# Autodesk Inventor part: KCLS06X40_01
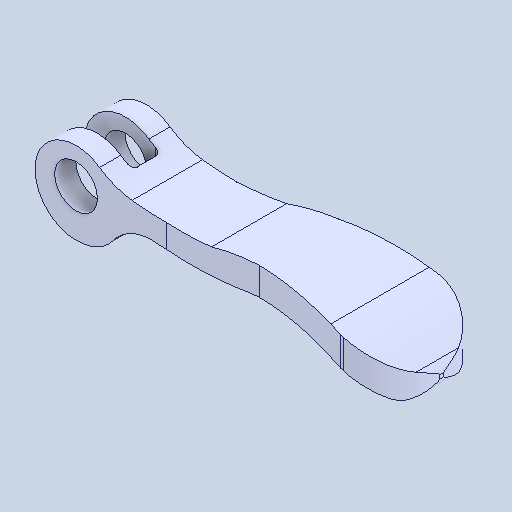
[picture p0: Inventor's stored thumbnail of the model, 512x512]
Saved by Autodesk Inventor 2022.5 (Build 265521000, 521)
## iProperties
Created: 2024-08
Part Number: KCLS06X40_01
Material: 一般
Document SubType Name: Modeling
Designer: ImaoCorp
Density: 1 g/cm^3
Appearance: 既定
Author: ImaoCorp
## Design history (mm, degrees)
feature "KCLS06X40_01"
node "ソリッド1"
